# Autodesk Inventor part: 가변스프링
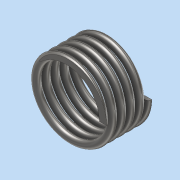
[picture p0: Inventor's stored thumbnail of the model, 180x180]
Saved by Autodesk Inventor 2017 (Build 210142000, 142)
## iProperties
Part Number: 가변스프링
Material: 스테인레스 스틸
Document SubType Name: Modeling
Designer: mrc
Mass: 7.49088 g
Surface Area: 19.5771 cm^2
Volume: 0.93636 cm^3
Density: 8 g/cm^3
Appearance: 반연마
Author: mrc
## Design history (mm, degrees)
sketch "스케치1"
  geometry: L1 (0, 0)-(0, 12.7); L2 (0, 12.7)-(10, 12.7); L3 (10, 12.7)-(10, 0); L4 (10, 0)-(0, 0); C1 r 1 at (10, 0)
  constraints: 8 end point, 3 perpendicular, 1 centre point, 1 coincident, 1 vertical
  dimensions: "d0" = 12.7 distance between parallel lines of L4 L2 (derived); "d1" = 20 diameter of L3 L1; "d2" = 2 diameter of C1
feature "코일1" sketch "스케치1" pitch "d3" = 10; turns "d5" = 5; dims "d4" = 12.7 (= d0), "d6" = 0, angle "d7" = 90 deg, angle "d8" = 90 deg, "d9" = 0, "d10" = 0
sketch "스케치2"
  geometry: L1 (12.7, 15.977)-(0, 15.977); L2 (0, 15.977)-(0, -15.977); L3 (0, -15.977)-(12.7, -15.977); L4 (12.7, -15.977)-(12.7, 15.977); 2 further points
  constraints: 8 end point, 2 midpoint, 2 parallel, 1 horizontal, 1 horizontal alignment, 1 perpendicular
  dimensions: "d11" = 31.95358 distance between parallel lines of L1 L3
extrude "돌출1" sketch "스케치2" stored distance "d12" = 0; taper "d13" = 0 deg
node "솔리드1"
